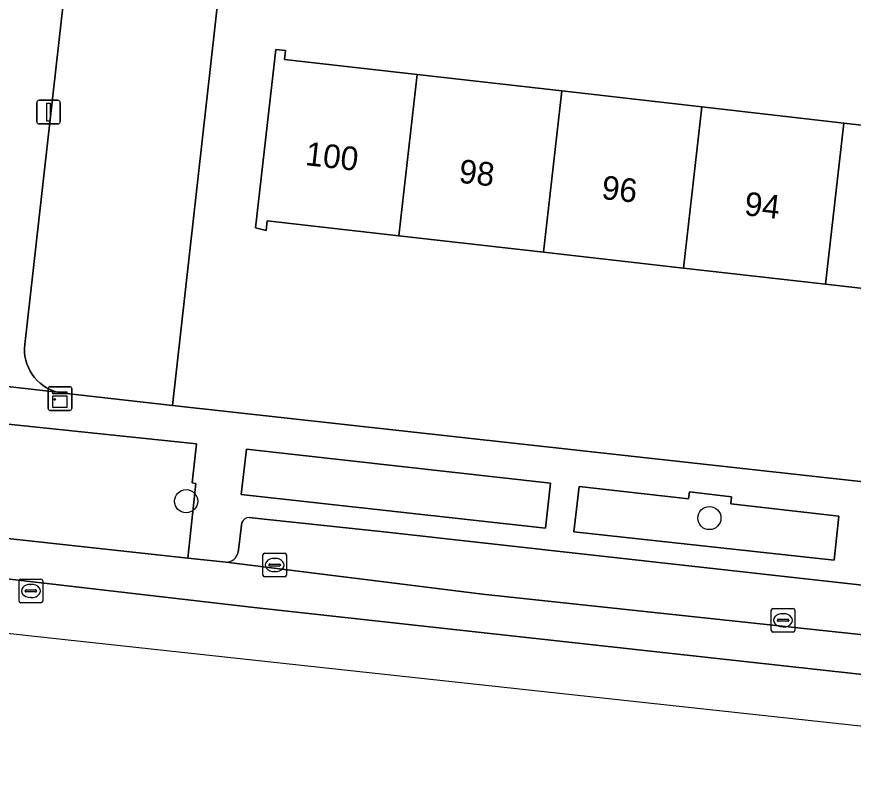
# Model space of a CAD drawing. Extents: x 162026 to 163502, y 387295 to 388169.
# Drawn here: x 162508.26 to 162543.67, y 387368.25 to 387400.44 of the extents above; entities that cross this region are included whole.
import ezdxf

# ---------------------------------------------------------------- set-up
doc = ezdxf.new("R2010")
doc.units = 0
for name, color, linetype in [('IMGEO_Boom', 7, 'Continuous'), ('IMGEO_Erf', 7, 'Continuous'), ('IMGEO_Groenvoorziening', 7, 'Continuous'), ('IMGEO_Kast', 7, 'Continuous'), ('IMGEO_Kolk', 7, 'Continuous'), ('IMGEO_Lichtmast', 7, 'Continuous'), ('IMGEO_Pand', 7, 'Continuous'), ('IMGEO_Pand_nummerreeks', 7, 'Continuous'), ('IMGEO_Parkeervlak_open', 7, 'Continuous'), ('IMGEO_Rijbaan_lokaal_gesloten', 7, 'Continuous'), ('IMGEO_Rijbaan_lokaal_open', 7, 'Continuous'), ('IMGEO_Rioolput', 7, 'Continuous'), ('IMGEO_Voetpad_open', 7, 'Continuous')]:
    doc.layers.add(name, color=color, linetype=linetype)

msp = doc.modelspace()

# ---------------------------------------------------------------- linework, layer by layer
at = {"layer": 'IMGEO_Boom'}
for centre in [(162515.43, 387379.939), (162537.578, 387379.224)]:
    msp.add_circle(centre, 0.489, dxfattribs=at)
at = {"layer": 'IMGEO_Erf'}
for points in [[(162517.916, 387411.315), (162514.853, 387383.996), (162565.941, 387378.346), (162566.197, 387378.329), (162566.453, 387378.335), (162566.707, 387378.364), (162566.958, 387378.415), (162567.204, 387378.489), (162567.442, 387378.584), (162567.67, 387378.7), (162567.887, 387378.836), (162568.091, 387378.991), (162568.281, 387379.163), (162568.454, 387379.352), (162568.61, 387379.556), (162568.747, 387379.772), (162568.864, 387380), (162568.96, 387380.238), (162569.035, 387380.483), (162569.087, 387380.733), (162569.106, 387380.869), (162571.901, 387405.298)], [(162548.55, 387388.427), (162542.492, 387389.118), (162536.481, 387389.803), (162530.554, 387390.478), (162524.426, 387391.176), (162518.866, 387391.81), (162518.818, 387391.394), (162518.368, 387391.51), (162519.229, 387399.063), (162519.632, 387399.017), (162519.589, 387398.639), (162525.204, 387397.999), (162531.332, 387397.301), (162537.259, 387396.625), (162543.27, 387395.94), (162549.328, 387395.25)]]:
    msp.add_lwpolyline(points, dxfattribs=at)
at = {"layer": 'IMGEO_Groenvoorziening'}
for points in [[(162514.853, 387383.996), (162517.916, 387411.315), (162511.463, 387412.025), (162508.596, 387386.572), (162508.585, 387386.405), (162508.588, 387386.238), (162508.607, 387386.072), (162508.64, 387385.908), (162508.688, 387385.748), (162508.75, 387385.593), (162508.826, 387385.444), (162508.914, 387385.302), (162509.015, 387385.169), (162509.127, 387385.046), (162509.25, 387384.932), (162509.383, 387384.831), (162509.524, 387384.741), (162509.673, 387384.665), (162509.827, 387384.602), (162509.987, 387384.553), (162510.151, 387384.519), (162510.251, 387384.505)], [(162502.899, 387383.719), (162502.394, 387378.935), (162507.888, 387378.356), (162515.504, 387377.53), (162515.843, 387380.694), (162515.685, 387380.71), (162515.866, 387382.364), (162510.06, 387382.973)], [(162517.753, 387380.224), (162530.647, 387378.798), (162530.848, 387380.703), (162517.978, 387382.146)], [(162531.837, 387378.644), (162542.857, 387377.447), (162543.062, 387379.312), (162538.491, 387379.832), (162538.52, 387380.123), (162536.732, 387380.33), (162536.697, 387380.037), (162532.065, 387380.557)]]:
    msp.add_lwpolyline(points, close=True, dxfattribs=at)
at = {"layer": 'IMGEO_Kast'}
for p, q in [((162509.585, 387383.858), (162509.585, 387384.699)), ((162509.585, 387384.699), (162509.585, 387383.858)), ((162509.66, 387384.783), (162510.501, 387384.783)), ((162510.501, 387384.783), (162509.66, 387384.783)), ((162510.585, 387384.708), (162510.585, 387383.867)), ((162510.585, 387383.867), (162510.585, 387384.708)), ((162510.51, 387383.783), (162509.669, 387383.783)), ((162509.669, 387383.783), (162510.51, 387383.783))]:
    msp.add_line(p, q, dxfattribs=at)
for points in [[(162509.78, 387384.573), (162510.38, 387384.573), (162510.38, 387384.488), (162509.78, 387384.488), (162509.78, 387384.573)], [(162509.78, 387384.398), (162510.38, 387384.398), (162510.38, 387383.909), (162509.78, 387383.909), (162509.78, 387384.398)]]:
    msp.add_lwpolyline(points, dxfattribs=at)
msp.add_circle((162509.864, 387384.247), 0.0377, dxfattribs=at)
for centre, start, end in [((162509.663, 387384.705), 92.4484, 184.2845), ((162509.663, 387384.705), 92.4484, 184.2845), ((162510.507, 387384.705), 2.4484, 94.2845), ((162510.507, 387384.705), 2.4484, 94.2845), ((162509.663, 387383.861), 182.4484, 274.2845), ((162509.663, 387383.861), 182.4484, 274.2845), ((162510.507, 387383.861), 272.4484, 4.2845), ((162510.507, 387383.861), 272.4484, 4.2845)]:
    msp.add_arc(centre, 0.0779, start, end, dxfattribs=at)
at = {"layer": 'IMGEO_Kolk'}
for p, q in [((162518.75, 387377.738), (162519.602, 387377.738)), ((162518.675, 387376.812), (162518.675, 387377.664)), ((162519.163, 387377.518), (162519.188, 387377.518)), ((162519.676, 387377.664), (162519.676, 387376.812)), ((162518.934, 387377.232), (162518.934, 387377.244)), ((162519.372, 387377.195), (162518.974, 387377.195)), ((162518.977, 387377.281), (162519.375, 387377.281)), ((162519.418, 387377.244), (162519.418, 387377.232)), ((162519.602, 387376.738), (162518.75, 387376.738)), ((162519.186, 387376.958), (162519.161, 387376.958)), ((162540.196, 387374.472), (162540.196, 387375.324)), ((162540.271, 387375.398), (162541.123, 387375.398)), ((162541.197, 387375.324), (162541.197, 387374.472)), ((162540.455, 387374.892), (162540.455, 387374.904)), ((162540.498, 387374.941), (162540.896, 387374.941)), ((162540.684, 387375.178), (162540.709, 387375.178)), ((162540.939, 387374.904), (162540.939, 387374.892)), ((162540.893, 387374.855), (162540.495, 387374.855)), ((162540.707, 387374.618), (162540.682, 387374.618)), ((162541.123, 387374.398), (162540.271, 387374.398))]:
    msp.add_line(p, q, dxfattribs=at)
for points in [[(162518.75, 387377.738), (162519.602, 387377.738)], [(162518.675, 387376.812), (162518.675, 387377.664)], [(162519.676, 387377.664), (162519.676, 387376.812)], [(162519.602, 387376.738), (162518.75, 387376.738)], [(162540.196, 387374.472), (162540.196, 387375.324)], [(162540.271, 387375.398), (162541.123, 387375.398)], [(162541.197, 387375.324), (162541.197, 387374.472)], [(162541.123, 387374.398), (162540.271, 387374.398)]]:
    msp.add_lwpolyline(points, dxfattribs=at)
for centre, radius, start, end in [((162518.752, 387377.662), 0.0765, 91.552, 178.448), ((162518.752, 387377.662), 0.0765, 91.552, 178.448), ((162519.6, 387377.662), 0.0765, 1.552, 88.448), ((162519.6, 387377.662), 0.0765, 1.552, 88.448), ((162518.974, 387377.241), 0.0403, 85.8775, 175.7526), ((162518.971, 387377.231), 0.0366, 178.938, 274.7102), ((162519.375, 387377.238), 0.043, 264.8664, 352.4533), ((162519.379, 387377.243), 0.0386, 1.7309, 96.639), ((162518.752, 387376.814), 0.0765, 181.552, 268.448), ((162518.752, 387376.814), 0.0765, 181.552, 268.448), ((162519.6, 387376.814), 0.0765, 271.552, 358.448), ((162519.6, 387376.814), 0.0765, 271.552, 358.448), ((162540.273, 387375.322), 0.0765, 91.552, 178.448), ((162540.273, 387375.322), 0.0765, 91.552, 178.448), ((162541.121, 387375.322), 0.0765, 1.552, 88.448), ((162541.121, 387375.322), 0.0765, 1.552, 88.448), ((162540.495, 387374.901), 0.0403, 85.8775, 175.7526), ((162540.9, 387374.903), 0.0386, 1.7309, 96.639), ((162540.492, 387374.891), 0.0366, 178.938, 274.7102), ((162540.896, 387374.898), 0.043, 264.8664, 352.4533), ((162540.273, 387374.474), 0.0765, 181.552, 268.448), ((162540.273, 387374.474), 0.0765, 181.552, 268.448), ((162541.121, 387374.474), 0.0765, 271.552, 358.448), ((162541.121, 387374.474), 0.0765, 271.552, 358.448)]:
    msp.add_arc(centre, radius, start, end, dxfattribs=at)
for centre, major_axis, ratio, start_param, end_param in [((162519.162, 387377.238), (-0.387, 0.002), 0.722429, 4.712389, 7.853982), ((162519.187, 387377.238), (-0.39, 0.002), 0.717154, 1.570796, 4.712389), ((162540.683, 387374.898), (-0.387, 0.002), 0.722429, 4.712389, 7.853982), ((162540.708, 387374.898), (-0.39, 0.002), 0.717154, 1.570796, 4.712389)]:
    msp.add_ellipse(centre, major_axis=major_axis, ratio=ratio, start_param=start_param, end_param=end_param, dxfattribs=at)
at = {"layer": 'IMGEO_Lichtmast'}
for p, q in [((162509.208, 387396.906), (162509.998, 387396.906)), ((162509.998, 387396.906), (162509.208, 387396.906)), ((162509.108, 387396.006), (162509.108, 387396.806)), ((162509.108, 387396.806), (162509.108, 387396.006)), ((162510.098, 387396.806), (162510.098, 387396.006)), ((162510.098, 387396.006), (162510.098, 387396.806)), ((162509.998, 387395.906), (162509.208, 387395.906)), ((162509.208, 387395.906), (162509.998, 387395.906))]:
    msp.add_line(p, q, dxfattribs=at)
msp.add_lwpolyline([(162509.528, 387396.781), (162509.678, 387396.781), (162509.678, 387396.031), (162509.528, 387396.031), (162509.528, 387396.781)], dxfattribs=at)
for centre, start, end in [((162509.208, 387396.806), 90, 180), ((162509.208, 387396.806), 90, 180), ((162509.998, 387396.806), 0, 90), ((162509.998, 387396.806), 360, 90), ((162509.208, 387396.006), 180, 270), ((162509.208, 387396.006), 180, 270), ((162509.998, 387396.006), 270, 0), ((162509.998, 387396.006), 270, 0)]:
    msp.add_arc(centre, 0.1, start, end, dxfattribs=at)
at = {"layer": 'IMGEO_Pand'}
for points in [[(162525.204, 387397.999), (162519.589, 387398.639), (162519.632, 387399.017), (162519.229, 387399.063), (162518.368, 387391.51), (162518.818, 387391.394), (162518.866, 387391.81), (162524.426, 387391.176)], [(162531.332, 387397.301), (162525.204, 387397.999), (162524.426, 387391.176), (162530.554, 387390.478)], [(162537.259, 387396.625), (162531.332, 387397.301), (162530.554, 387390.478), (162536.481, 387389.803)], [(162536.481, 387389.803), (162542.492, 387389.118), (162543.27, 387395.94), (162537.259, 387396.625)], [(162542.492, 387389.118), (162548.55, 387388.427), (162549.328, 387395.25), (162543.27, 387395.94)]]:
    msp.add_lwpolyline(points, close=True, dxfattribs=at)
at = {"layer": 'IMGEO_Parkeervlak_open'}
for points in [[(162523.796, 387378.637), (162518.604, 387379.187), (162518.095, 387379.252)], [(162517.784, 387379.042), (162517.638, 387377.77)], [(162566.389, 387373.92), (162554.945, 387375.167), (162523.796, 387378.637)], [(162517.123, 387377.359), (162527.979, 387376.004), (162566.814, 387371.862), (162566.892, 387371.857), (162567.004, 387371.854)]]:
    msp.add_lwpolyline(points, dxfattribs=at)
for centre, radius, start, end in [((162518.108, 387378.898), 0.354, 92.0396, 156.0181), ((162517.112, 387377.901), 0.542, 271.1553, 346.0285)]:
    msp.add_arc(centre, radius, start, end, dxfattribs=at)
at = {"layer": 'IMGEO_Rijbaan_lokaal_gesloten'}
msp.add_lwpolyline([(162492.641, 387378.303), (162507.846, 387376.647), (162518.186, 387375.46), (162559.818, 387370.862), (162564.23, 387370.379), (162566.622, 387370.117), (162566.814, 387371.862), (162527.979, 387376.004), (162517.123, 387377.359), (162515.504, 387377.53), (162507.888, 387378.356), (162502.394, 387378.935), (162500.773, 387379.123), (162494.229, 387379.882)], dxfattribs=at)
at = {"layer": 'IMGEO_Rijbaan_lokaal_open'}
for points in [[(162388.45, 387391.853), (162377.842, 387394.075), (162376.939, 387394.301), (162376.19, 387390.853), (162376.19, 387390.853), (162381.469, 387390.258), (162453.483, 387380.638), (162463.978, 387379.236), (162499.096, 387375.311), (162499.096, 387375.311), (162509.658, 387374.162), (162563.988, 387368.254)], [(162563.988, 387368.254), (162564.23, 387370.379), (162559.818, 387370.862), (162518.186, 387375.46), (162507.846, 387376.647), (162492.641, 387378.303)]]:
    msp.add_lwpolyline(points, dxfattribs=at)
at = {"layer": 'IMGEO_Rioolput'}
for p, q in [((162508.358, 387375.714), (162508.358, 387376.566)), ((162508.433, 387376.64), (162509.285, 387376.64)), ((162508.846, 387376.42), (162508.871, 387376.42)), ((162509.359, 387376.566), (162509.359, 387375.714)), ((162508.617, 387376.134), (162508.617, 387376.146)), ((162509.055, 387376.097), (162508.657, 387376.097)), ((162508.66, 387376.183), (162509.058, 387376.183)), ((162509.101, 387376.146), (162509.101, 387376.134)), ((162509.285, 387375.64), (162508.433, 387375.64)), ((162508.869, 387375.86), (162508.844, 387375.86))]:
    msp.add_line(p, q, dxfattribs=at)
for points in [[(162508.358, 387375.714), (162508.358, 387376.566)], [(162508.433, 387376.64), (162509.285, 387376.64)], [(162509.359, 387376.566), (162509.359, 387375.714)], [(162509.285, 387375.64), (162508.433, 387375.64)]]:
    msp.add_lwpolyline(points, dxfattribs=at)
for centre, radius, start, end in [((162508.435, 387376.564), 0.0765, 91.552, 178.448), ((162508.435, 387376.564), 0.0765, 91.552, 178.448), ((162509.283, 387376.564), 0.0765, 1.552, 88.448), ((162509.283, 387376.564), 0.0765, 1.552, 88.448), ((162508.657, 387376.143), 0.0403, 85.8775, 175.7526), ((162508.654, 387376.133), 0.0366, 178.938, 274.7102), ((162509.058, 387376.14), 0.043, 264.8664, 352.4533), ((162509.062, 387376.145), 0.0386, 1.7309, 96.639), ((162508.435, 387375.716), 0.0765, 181.552, 268.448), ((162508.435, 387375.716), 0.0765, 181.552, 268.448), ((162509.283, 387375.716), 0.0765, 271.552, 358.448), ((162509.283, 387375.716), 0.0765, 271.552, 358.448)]:
    msp.add_arc(centre, radius, start, end, dxfattribs=at)
for centre, major_axis, ratio, start_param, end_param in [((162508.845, 387376.14), (-0.387, 0.002), 0.722429, 4.712389, 7.853982), ((162508.87, 387376.14), (-0.39, 0.002), 0.717154, 1.570796, 4.712389)]:
    msp.add_ellipse(centre, major_axis=major_axis, ratio=ratio, start_param=start_param, end_param=end_param, dxfattribs=at)
at = {"layer": 'IMGEO_Voetpad_open'}
for points in [[(162503.26, 387385.31), (162509.987, 387384.553), (162509.827, 387384.602), (162509.673, 387384.665), (162509.524, 387384.741), (162509.383, 387384.831), (162509.25, 387384.932), (162509.127, 387385.046), (162509.015, 387385.169), (162508.914, 387385.302), (162508.826, 387385.444), (162508.75, 387385.593), (162508.688, 387385.748), (162508.64, 387385.908), (162508.607, 387386.072), (162508.588, 387386.238), (162508.585, 387386.405), (162508.596, 387386.572), (162511.463, 387412.025), (162511.63, 387413.504), (162514.018, 387434.709)], [(162503.031, 387385.319), (162502.899, 387383.719), (162510.06, 387382.973), (162515.866, 387382.364), (162515.685, 387380.71), (162515.843, 387380.694), (162515.504, 387377.53), (162517.123, 387377.359)], [(162573.591, 387377.545), (162565.941, 387378.346), (162514.853, 387383.996), (162510.251, 387384.505), (162510.151, 387384.519), (162509.987, 387384.553), (162503.26, 387385.31)], [(162518.095, 387379.252), (162518.604, 387379.187), (162523.796, 387378.637), (162554.945, 387375.167), (162566.389, 387373.92)], [(162517.638, 387377.77), (162517.784, 387379.042)]]:
    msp.add_lwpolyline(points, dxfattribs=at)
for points in [[(162517.753, 387380.224), (162517.978, 387382.146), (162530.848, 387380.703), (162530.647, 387378.798)], [(162531.837, 387378.644), (162532.065, 387380.557), (162536.697, 387380.037), (162536.732, 387380.33), (162538.52, 387380.123), (162538.491, 387379.832), (162543.062, 387379.312), (162542.857, 387377.447)]]:
    msp.add_lwpolyline(points, close=True, dxfattribs=at)
for centre, radius, start, end in [((162518.108, 387378.898), 0.354, 92.0396, 156.0181), ((162517.112, 387377.901), 0.542, 271.1553, 346.0285)]:
    msp.add_arc(centre, radius, start, end, dxfattribs=at)

# ---------------------------------------------------------------- texts
at = {"layer": 'IMGEO_Pand_nummerreeks'}
for s, p in [('100', (162520.441, 387394.167)), ('98', (162526.942, 387393.425)), ('96', (162532.983, 387392.737)), ('94', (162539.027, 387392.049))]:
    msp.add_text(s, height=1, rotation=353.4985, dxfattribs=at).set_placement(p)

doc.saveas('drawing.dxf')
